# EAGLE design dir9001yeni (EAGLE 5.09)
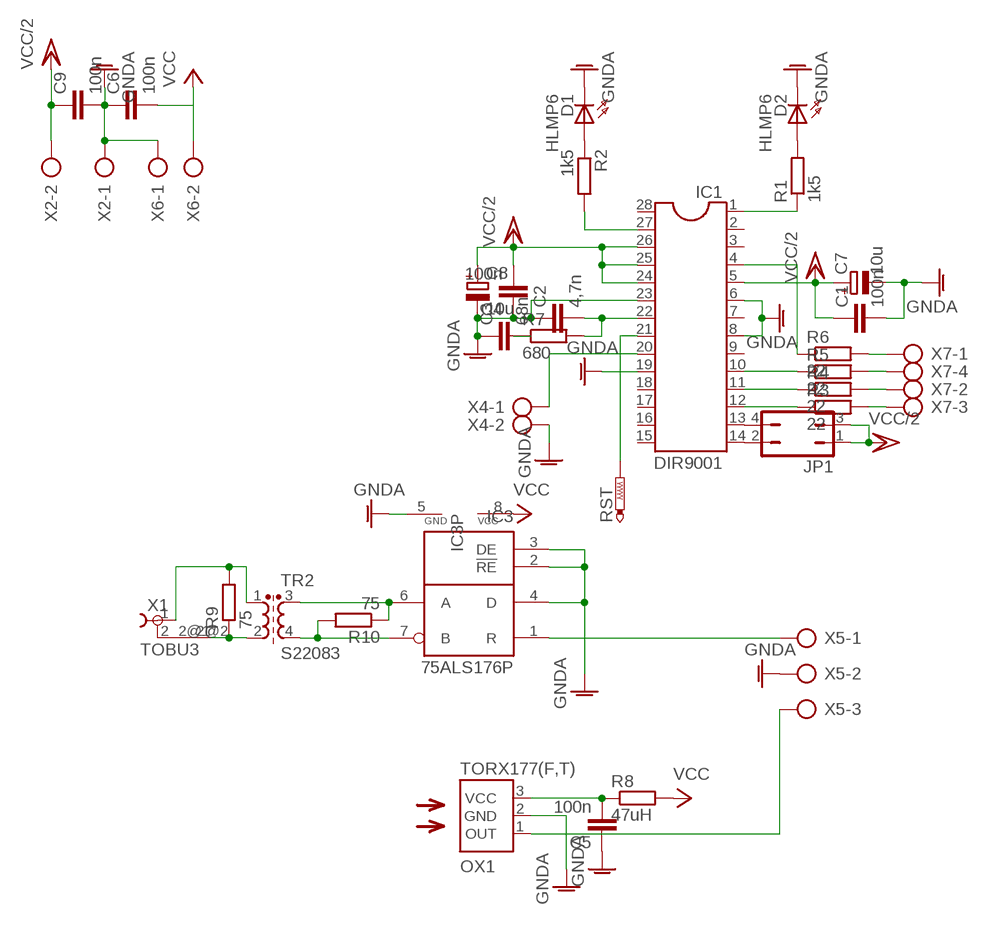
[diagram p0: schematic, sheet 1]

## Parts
C1  100n  C5/2.5  [C5B2.5]
C2  4,7n  C5/2.5  [C5B2.5]
C3  68n  C5/2.5  [C5B2.5]
C4  100n  C5/2.5  [C5B2.5]
C5  100n  C5/2.5  [C5B2.5]
C6  100n  C5/2.5  [C5B2.5]
C7  10u  CPOL-EUTAP5-50  [TAP5-50]
C8  10u  CPOL-EUE5-5  [E5-5]
C9  100n  C5/2.5  [C5B2.5]
D1  HLMP6  [HLMP6]
D2  HLMP6  [HLMP6]
IC1  DIR9001  DIL28  [DIL28-6]
IC3  75ALS176P  [DIL08]
JP1  JP2Q  [JP2Q]
OX1  TORX177(F,T)  [TORX]
R1  1k5  R-EU_0207/10  [0207/10]
R2  1k5  R-EU_0207/10  [0207/10]
R3  22  R-EU_0207/10  [0207/10]
R4  22  R-EU_0207/10  [0207/10]
R5  22  R-EU_0207/10  [0207/10]
R6  22  R-EU_0204/7  [0204/7]
R7  680  R-EU_0207/10  [0207/10]
R8  47uH  R-EU_0207/12  [0207/12]
R9  75  R-EU_0207/10  [0207/10]
R10  75  R-EU_0207/10  [0207/10]
RST  PTR1PAD1-13Y  [P1-13Y]
TR2  S22083  [S22083]
X1  TOBU3  [TOBU3]
X2  AK500/2  [AK500/2]
X4  AK500/2  [AK500/2]
X5  AK500/3  [AK500/3]
X6  AK500/2  [AK500/2]
X7  AK500/4  [AK500/4]

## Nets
GNDA: C1.2 C2.1 C3.1 C4.1 C5.1 C6.1 C7.- C8.- C9.2 D1.K D2.K IC1.6 IC1.8 IC1.19 IC1.23 IC3.2(!RE) IC3.3(DE) IC3.4(D) IC3.5(GND) OX1.2(GND) X2.1 X4.2 X5.2 X6.1
N$1: IC1.1 R1.1
N$2: IC1.27 R2.2
N$3: IC1.12 R3.1
N$4: IC1.11 R4.1
N$5: IC1.10 R5.1
N$6: IC1.4 R6.1
N$7: IC3.7(B) R10.2 TR2.4
N$8: IC3.6(A) R10.1 TR2.3
N$10: IC1.21 RST.TP
N$12: C2.2 IC1.22 R7.2
N$14: C3.2 R7.1
N$15: R4.2 X7.2
N$16: R3.2 X7.3
N$18: C5.2 OX1.3(VCC) R8.1
N$19: D1.A R2.1
N$20: D2.A R1.2
N$21: R5.2 X7.4
N$22: IC1.20 X4.1
N$23: OX1.1(OUT) X5.3
N$24: R6.2 X7.1
N$25: R9.1 TR2.2 X1.2@2
N$26: IC3.1(R) X5.1
N$27: R9.2 TR2.1 X1.1
N$28: IC1.14 JP1.2
N$29: IC1.13 JP1.4
VCC: C6.2 IC3.8(VCC) R8.2 X6.2
VCC/2: C1.1 C4.2 C7.+ C8.+ C9.1 IC1.5 IC1.24 IC1.25 IC1.26 JP1.1 JP1.3 X2.2
Unconnected: IC1.2 IC1.3 IC1.7 IC1.9 IC1.15 IC1.16 IC1.17 IC1.18 IC1.28 X1.2 X1.2@1

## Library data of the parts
C1-C6 C9 = capacitor-wima:C: CAPACITOR
C7 C8 = resistor:CPOL-EU: POLARIZED CAPACITOR, European symbol
D1 D2 = display-hp:HLMP6: LED
IC1 = ic-package:DIL28: Dual In Line
IC3 = texas:75ALS176: DIFFERENTIAL BUS TRANSCEIVERS TIA/EIA-422-B, TIA/EIA-422-B + TIA/EIA-422-B TIA/EIA-422-B Operate at Data Rates up to 35 Mbaud Source: http://focus.ti.com/lit/ds/symlink/sn65als176.pdf
JP1 = jumper:JP2Q: JUMPER
OX1 = pavouk:TORX177(F,T): FIBER OPTIC RECEIVING MODULE
R1-R10 = resistor:R-EU_: RESISTOR, European symbol
RST = testpad:PTR1: TEST PIN
TR2 = pavouk:S22083: Newava S22083 1:1 Pulse transformer
X1 = con-hirschmann:TOBU3: Female Cinch CONNECTOR ( RCA Jack )
X2 X4 X6 = con-ptr500:AK500/2: CONNECTOR
X5 = con-ptr500:AK500/3: CONNECTOR
X7 = con-ptr500:AK500/4: CONNECTOR

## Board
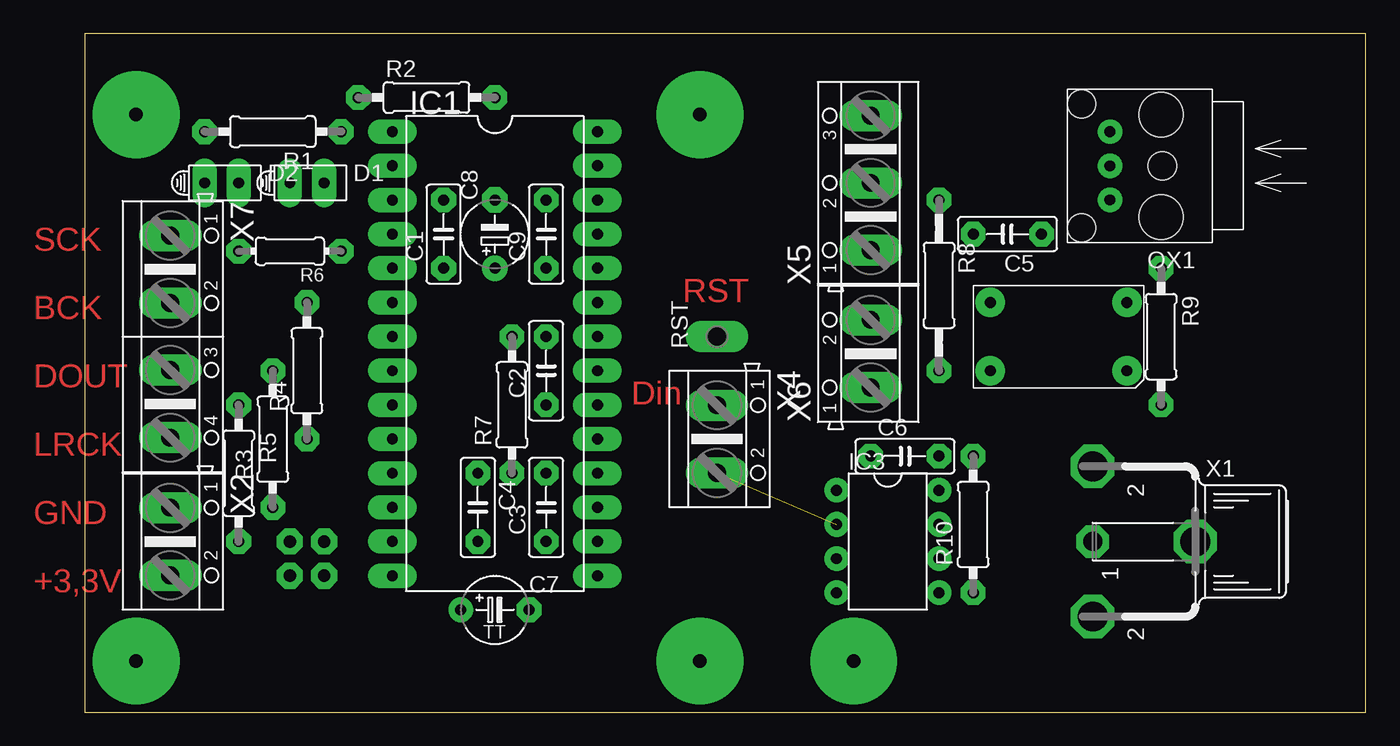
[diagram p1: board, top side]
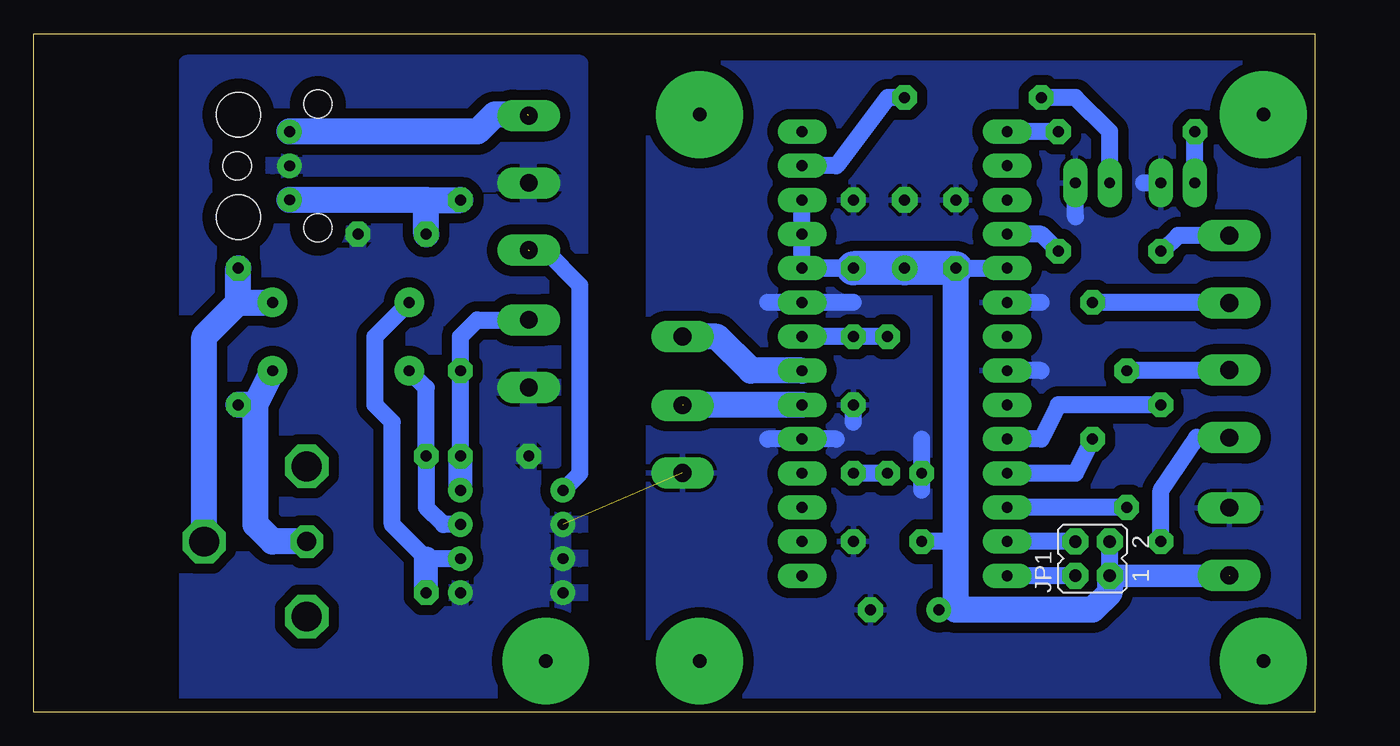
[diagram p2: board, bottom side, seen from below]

Size 95.23 x 50.47 mm. Coordinates in mm from the lower left corner, seen from the top.
Outline: 0,0 95.23,0 95.23,50.47 0,50.47 0,0
Copper layers (1*16): Top 0.035mm / dielectric 1.5mm / Bottom 0.035mm
Design rules "default *": minimum track width 20mil, minimum drill 24mil, track to track 30mil, track to pad 30mil, pad to pad 30mil, via to via 30mil, smd to smd 20mil, copper to edge 40mil, drill to drill 20mil, minimum pad ring 20mil, minimum via ring 20mil, stop-mask expansion 4mil, vias tented up to drill 0mil, thermal gap 10mil

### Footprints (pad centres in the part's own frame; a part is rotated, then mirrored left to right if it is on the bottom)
C5B2.5 = drill 0.813 pad 1.6 octagon: 1 -2.54,0; 2 2.54,0
TAP5-50 = drill 0.813 round: + -2.54,0 | drill 0.813 octagon: - 2.54,0
E5-5 = drill 0.813 pad 1.905 round: + -2.54,0 | drill 0.813 pad 1.905 octagon: - 2.54,0
HLMP6 = drill 0.813 long: A -1.27,0; K 1.27,0
DIL28-6 = drill 0.813 long: 1 -16.51,-7.62; 2 -13.97,-7.62; 3 -11.43,-7.62; 4 -8.89,-7.62; 5 -6.35,-7.62; 6 -3.81,-7.62; 7 -1.27,-7.62; 8 1.27,-7.62; 9 3.81,-7.62; 10 6.35,-7.62; 11 8.89,-7.62; 12 11.43,-7.62; 13 13.97,-7.62; 14 16.51,-7.62; 15 16.51,7.62; 16 13.97,7.62; 17 11.43,7.62; 18 8.89,7.62; 19 6.35,7.62; 20 3.81,7.62; 21 1.27,7.62; 22 -1.27,7.62; 23 -3.81,7.62; 24 -6.35,7.62; 25 -8.89,7.62; 26 -11.43,7.62; 27 -13.97,7.62; 28 -16.51,7.62
DIL08 = drill 0.813 pad 1.27 round: 1 -3.81,-3.81; 2 -1.27,-3.81; 3 1.27,-3.81; 4 3.81,-3.81; 5 3.81,3.81; 6 1.27,3.81; 7 -1.27,3.81; 8 -3.81,3.81
JP2Q = drill 0.914 octagon: 1 -1.27,-1.27; 2 -1.27,1.27; 3 1.27,-1.27; 4 1.27,1.27
TORX = drill 0.8 pad 1.676 round: 1 3.81,-2.54; 2 3.81,0; 3 3.81,2.54 | hole 3.3: 0,3.81; 0,-3.81 | hole 2.1: -0.09,0; 5.91,4.6; 5.91,-4.6
0207/10 = drill 0.813 octagon: 1 -5.08,0; 2 5.08,0
0204/7 = drill 0.813 octagon: 1 -3.81,0; 2 3.81,0
0207/12 = drill 0.813 octagon: 1 -6.35,0; 2 6.35,0
P1-13Y = drill 1.321 pad 1.905 long: TP 0,0
S22083 = drill 0.8 pad 2.184 round: 1 -5.08,2.54; 2 -5.08,-2.54; 3 5.08,-2.54; 4 5.08,2.54
TOBU3 = drill 1.397 octagon: 1 0,-2.54 | drill 2.21 octagon: 2 5.588,-2.54; 2@1 -5.588,-2.54; 2@2 0,5.08
AK500/2 = drill 1.321 long: 1 -2.515,0; 2 2.515,0
AK500/3 = drill 1.321 long: 1 -5.004,0; 2 0,0; 3 5.004,0
AK500/4 = drill 1.321 long: 1 -7.518,0; 2 -2.489,0; 3 2.489,0; 4 7.518,0

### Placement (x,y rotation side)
C1  26.67,35.56 90 top
C2  34.29,25.4 90 top
C3  34.29,15.24 90 top
C4  29.21,15.24 270 top
C5  68.58,35.56 180 top
C6  60.96,19.05 0 top
C7  30.48,7.62 0 top
C8  30.48,35.56 90 top
C9  34.29,35.56 90 top
D1  16.51,39.37 0 top
D2  10.16,39.37 0 top
IC1  30.48,26.67 270 top
IC3  59.69,12.7 270 top
JP1  16.51,11.43 90 bottom
OX1  80.01,40.64 180 top
R1  13.97,43.18 180 top
R2  25.4,45.72 0 top
R3  13.97,20.32 90 top
R4  16.51,25.4 90 top
R5  11.43,17.78 270 top
R6  15.24,34.29 180 top
R7  31.75,22.86 90 top
R8  63.5,31.75 270 top
R9  80.01,27.94 270 top
R10  66.04,13.97 90 top
RST  46.99,27.94 90 top
TR2  72.39,27.94 180 top
X1  77.47,12.7 270 top
X2  6.35,12.7 270 top
X4  46.99,20.32 270 top
X5  58.42,39.37 90 top
X6  58.42,26.67 90 top
X7  6.35,27.94 270 top

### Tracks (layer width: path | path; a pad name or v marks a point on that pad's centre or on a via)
GNDA  (1 unrouted)
  Bottom 1.27: 20.32,30.48 IC1.6 | 34.29,30.48 IC1.23 40.64,30.48 | 40.64,20.32 IC1.19 35.56,20.32 | 34.29,21.59 C2.1 | 20.32,25.4 IC1.8 | 29.21,16.51 C4.1 29.21,20.32 | 17.78,36.83 D1.K | D2.K 12.7,39.37
  pour Bottom: 49.53,0 0,0 0,48.26 49.53,48.26
  pour Bottom: 83.82,1.27 54.61,1.27 54.61,48.26 83.82,48.26
N$1
  Bottom 1.27: R1.1 IC1.1
N$2
  Bottom 1.27: IC1.27 35.56,40.64 31.75,45.72 R2.2
N$3
  Bottom 1.27: R3.1 IC1.12
N$4
  Bottom 1.27: IC1.11 17.78,17.78 R4.1
N$5
  Bottom 1.27: IC1.10 20.32,20.32 19.05,22.86 R5.1
N$6
  Bottom 1.27: IC1.4 20.32,35.56 R6.1
N$7
  Bottom 1.27: IC3.7 64.77,13.97 66.04,15.24 R10.2 66.04,24.13 TR2.4
N$8
  Bottom 1.27: IC3.6 66.04,11.43 68.58,13.97 68.58,21.59 69.85,22.86 69.85,27.94 TR2.3
  Bottom 1.778: R10.1 66.04,11.43
N$10
  Bottom 1.93: IC1.21 41.91,25.4 44.45,27.94 RST.TP
N$12
  Bottom 1.27: IC1.22 C2.2 R7.2
N$14
  Bottom 1.27: R7.1 C3.2
N$15
  Bottom 1.27: R4.2 6.4,30.48 X7.2
N$16
  Bottom 1.27: R3.2 12.72,25.43 6.38,25.43 X7.3
N$18
  Bottom 1.93: 66.04,38.1 R8.1 | 66.04,38.1 OX1.3 | C5.2 66.04,38.1
N$19
  Bottom 1.27: D1.A 15.24,43.18 17.78,45.72 R2.1
N$20
  Bottom 1.27: D2.A R1.2
N$21
  Bottom 1.27: R5.2 11.43,16.51 8.76,20.45 6.38,20.45 X7.4
N$22  (1 unrouted)
  Bottom 1.93: IC1.20 46.97,22.86
N$23  (1 unrouted)
  Bottom 1.93: 58.5,44.45 60.96,44.45 62.23,43.18 OX1.1
N$24
  Bottom 1.27: R6.2 11.3,34.29 10.13,35.46 X7.1
N$25
  Bottom 1.93: X1.2@2 82.55,27.94 80.01,30.48 | 80.01,30.48 TR2.2 | 80.01,30.48 R9.1
N$26  (1 unrouted)
  Bottom 1.27: IC3.1 54.61,17.78 54.61,31.75 57.15,34.29 58.34,34.29
N$27
  Bottom 1.93: 78.74,22.86 TR2.1 | 78.74,22.86 78.74,13.97 77.47,12.7 X1.1 | 78.74,22.86 R9.2
N$28
  Bottom 1.27: JP1.2 IC1.14
N$29
  Bottom 1.27: JP1.4 IC1.13
N$30  (via drill 1 pad 6.45)
  other vias: 45.72,3.81
N$31  (via drill 1 pad 6.45)
  other vias: 3.81,3.81
N$32  (via drill 1 pad 6.45)
  other vias: 45.72,44.45
N$33  (via drill 1 pad 6.45)
  other vias: 3.81,44.45
N$35  (via drill 1 pad 6.45)
  other vias: 57.15,3.81
VCC
  Bottom 1.27: X6.2 62.26,29.18 63.5,27.94 R8.2 C6.2
  Bottom 1.778: IC3.8 C6.2
VCC/2  (1 unrouted)
  Bottom 1.016: 26.67,25.4 26.67,25.57
  Bottom 1.27: IC1.26 IC1.25 IC1.24 | JP1.1 JP1.3 | C8.+ IC1.24 | IC1.24 C9.1 | C1.1 IC1.5 | 6.4,10.16 6.35,10.16 | 26.67,12.7 C4.2 | 26.67,7.62 C7.+
  Bottom 1.676: 6.4,10.16 JP1.1
  Bottom 1.93: C1.1 26.67,26.5 26.67,25.4 26.67,12.7 26.67,7.62 16.51,7.62 15.24,8.89 JP1.1
  Bottom 2.54: C9.1 C8.+ C1.1

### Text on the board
Top: SCK | RST | BCK | DOUT | Din | LRCK | GND | +3,3V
